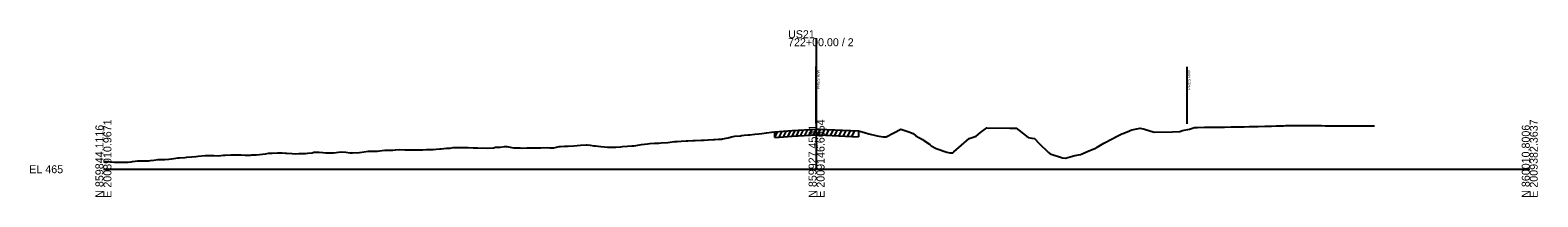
# Model space of a CAD drawing. Extents: x 2008702 to 2066449, y 841632 to 857812.
# Drawn here: x 2065921 to 2066449, y 844204 to 844262 of the extents above; entities that cross this region are included whole.
import ezdxf

# ---------------------------------------------------------------- set-up
doc = ezdxf.new("R2010")
doc.units = 0
for name, color, linetype in [('RD_GPK_XS_Cell', 7, 'Continuous'), ('RD_XS_ExGround', 7, 'Continuous'), ('RD_XS_ExPaveRet', 7, 'Continuous'), ('RD_XS_TX_Box', 7, 'Continuous'), ('RD_XS_TX_Elev_EX', 7, 'Continuous')]:
    doc.layers.add(name, color=color, linetype=linetype)

msp = doc.modelspace()

# ---------------------------------------------------------------- linework, layer by layer
at = {"layer": 'RD_GPK_XS_Cell'}
for p, q in [((2066196.51, 844213.53), (2066196.51, 844259.5)), ((2065946.51, 844213.53), (2066196.51, 844213.53)), ((2066196.51, 844213.53), (2066446.51, 844213.53))]:
    msp.add_line(p, q, dxfattribs=at)
at = {"layer": 'RD_XS_ExGround'}
msp.add_lwpolyline([(2065946.51, 844216.24), (2065947.1, 844216.25), (2065947.63, 844216.22), (2065950.28, 844215.98), (2065952.55, 844215.99), (2065953.46, 844216.04), (2065955.13, 844216.07), (2065956.25, 844216.15), (2065956.65, 844216.21), (2065958.6, 844216.51), (2065959.83, 844216.48), (2065962.4, 844216.52), (2065963.01, 844216.56), (2065964.13, 844216.68), (2065965.66, 844216.92), (2065966.19, 844216.94), (2065968.01, 844217), (2065969.38, 844217.05), (2065970.36, 844217.13), (2065972.71, 844217.52), (2065973.13, 844217.55), (2065975.06, 844217.62), (2065975.74, 844217.73), (2065977.41, 844217.88), (2065978.92, 844217.97), (2065979.76, 844218.07), (2065982.13, 844218.33), (2065985.29, 844218.34), (2065986.82, 844218.29), (2065988.47, 844218.45), (2065989.17, 844218.48), (2065991.13, 844218.55), (2065991.65, 844218.55), (2065993.87, 844218.54), (2065994.84, 844218.56), (2065996.22, 844218.45), (2065998.02, 844218.49), (2065998.57, 844218.6), (2066000.13, 844218.6), (2066001.2, 844218.65), (2066003.27, 844218.97), (2066004.39, 844219.16), (2066005.63, 844219.17), (2066007.57, 844219.28), (2066007.98, 844219.32), (2066009.13, 844219.26), (2066010.33, 844219.17), (2066010.75, 844219.17), (2066012.68, 844219.05), (2066013.93, 844218.97), (2066015.03, 844219.06), (2066017.38, 844219.05), (2066018.13, 844219.19), (2066019.73, 844219.32), (2066020.3, 844219.49), (2066022.08, 844219.47), (2066023.48, 844219.39), (2066024.44, 844219.26), (2066026.79, 844219.24), (2066027.13, 844219.28), (2066029.85, 844219.58), (2066031.49, 844219.51), (2066033.03, 844219.32), (2066033.84, 844219.31), (2066036.25, 844219.38), (2066039.39, 844219.92), (2066041.18, 844219.87), (2066042.58, 844219.87), (2066043.24, 844219.94), (2066045.14, 844220.17), (2066045.76, 844220.24), (2066047.95, 844220.17), (2066048.94, 844220.34), (2066050.3, 844220.51), (2066052.12, 844220.31), (2066054.14, 844220.29), (2066055, 844220.35), (2066055.31, 844220.32), (2066057.35, 844220.39), (2066058.49, 844220.32), (2066059.7, 844220.41), (2066061.67, 844220.46), (2066062.05, 844220.47), (2066063.14, 844220.56), (2066064.41, 844220.67), (2066064.85, 844220.71), (2066066.76, 844220.94), (2066068.04, 844220.95), (2066069.11, 844221.11), (2066071.46, 844221.2), (2066072.14, 844221.19), (2066073.81, 844221.12), (2066074.4, 844221.17), (2066076.16, 844221.03), (2066077.59, 844220.99), (2066081.14, 844220.91), (2066083.22, 844221.08), (2066083.95, 844221.23), (2066085.57, 844221.31), (2066087.13, 844221.53), (2066087.92, 844221.47), (2066090.32, 844221.02), (2066092.62, 844221.05), (2066093.5, 844220.9), (2066094.97, 844221), (2066096.68, 844221.02), (2066097.32, 844221.04), (2066099.14, 844221.04), (2066099.86, 844221.07), (2066102.03, 844221.15), (2066103.05, 844221.03), (2066104.38, 844221.07), (2066106.23, 844221.47), (2066106.73, 844221.55), (2066108.14, 844221.62), (2066109.08, 844221.67), (2066109.41, 844221.66), (2066111.43, 844221.79), (2066112.59, 844221.87), (2066113.78, 844221.93), (2066115.78, 844222.13), (2066116.13, 844222.11), (2066117.14, 844222), (2066118.48, 844221.8), (2066118.96, 844221.76), (2066120.83, 844221.52), (2066122.14, 844221.34), (2066123.19, 844221.32), (2066125.54, 844221.29), (2066126.14, 844221.32), (2066127.89, 844221.44), (2066128.51, 844221.48), (2066130.24, 844221.61), (2066131.69, 844221.69), (2066132.59, 844221.8), (2066135.14, 844222.21), (2066137.29, 844222.48), (2066138.05, 844222.59), (2066139.64, 844222.71), (2066141.24, 844222.73), (2066142, 844222.78), (2066144.42, 844222.94), (2066146.7, 844223.22), (2066147.6, 844223.28), (2066149.05, 844223.4), (2066150.79, 844223.51), (2066151.4, 844223.5), (2066153.14, 844223.56), (2066153.97, 844223.59), (2066156.1, 844223.72), (2066157.15, 844223.79), (2066158.45, 844223.88), (2066160.33, 844223.95), (2066160.81, 844224), (2066162.14, 844224.04), (2066163.16, 844224.1), (2066163.52, 844224.15), (2066165.51, 844224.57), (2066166.7, 844224.87), (2066167.86, 844225.11), (2066169.88, 844225.29), (2066170.21, 844225.34), (2066171.14, 844225.45), (2066172.56, 844225.61), (2066173.06, 844225.66), (2066174.91, 844225.83), (2066176.25, 844225.95), (2066177.26, 844226.05), (2066178.92, 844226.3), (2066180.69, 844226.52), (2066181.92, 844226.7), (2066187.96, 844227.09), (2066196.51, 844227.62), (2066196.82, 844227.64), (2066197.32, 844227.62), (2066211.2, 844226.95), (2066213.35, 844226.38), (2066214.88, 844225.96), (2066217.8, 844225.21), (2066219.91, 844224.95), (2066220.44, 844224.95), (2066220.91, 844224.95), (2066223.54, 844226.32), (2066225.99, 844227.56), (2066228.89, 844226.68), (2066230.35, 844226.11), (2066231.34, 844225.21), (2066233.69, 844223.95), (2066234.14, 844223.63), (2066236.04, 844222.33), (2066236.72, 844221.75), (2066238.4, 844220.75), (2066242.15, 844219.52), (2066243.26, 844219.28), (2066244.26, 844219.28), (2066244.67, 844219.66), (2066250.05, 844224.29), (2066250.7, 844224.5), (2066252.41, 844225.12), (2066254.03, 844226.38), (2066256.16, 844228.08), (2066264.26, 844227.96), (2066266.51, 844227.92), (2066267.43, 844227.2), (2066270.63, 844224.63), (2066271.92, 844224.46), (2066272.85, 844224.33), (2066274.54, 844222.61), (2066277.78, 844219.39), (2066278.39, 844218.91), (2066282.76, 844217.54), (2066283.82, 844217.46), (2066287, 844218.35), (2066288.98, 844218.75), (2066289.64, 844218.99), (2066291.93, 844220), (2066294, 844220.8), (2066294.82, 844221.3), (2066297.21, 844222.7), (2066300.37, 844224.34), (2066301.88, 844225.08), (2066303.55, 844225.9), (2066304.23, 844226.24), (2066306.15, 844227.01), (2066306.73, 844227.23), (2066307.05, 844227.33), (2066309.92, 844227.96), (2066311.5, 844227.61), (2066314.87, 844226.53), (2066321.29, 844226.66), (2066323.86, 844226.73), (2066324.76, 844227.17), (2066327.23, 844227.65), (2066329.01, 844228.16), (2066330.09, 844228.21), (2066332.44, 844228.24), (2066333.15, 844228.25), (2066334.79, 844228.28), (2066335.38, 844228.29), (2066337.15, 844228.32), (2066338.56, 844228.32), (2066339.5, 844228.33), (2066341.85, 844228.36), (2066342.15, 844228.37), (2066344.92, 844228.41), (2066346.44, 844228.45), (2066348.11, 844228.49), (2066351.29, 844228.55), (2066353.6, 844228.59), (2066354.47, 844228.6), (2066355.96, 844228.66), (2066357.65, 844228.74), (2066358.31, 844228.76), (2066360.15, 844228.81), (2066360.84, 844228.82), (2066363.01, 844228.83), (2066364.02, 844228.85), (2066365.36, 844228.83), (2066367.2, 844228.85), (2066367.71, 844228.84), (2066369.15, 844228.85), (2066370.06, 844228.84), (2066370.39, 844228.84), (2066372.41, 844228.82), (2066373.57, 844228.82), (2066374.77, 844228.81), (2066376.75, 844228.8), (2066377.12, 844228.79), (2066378.15, 844228.79), (2066379.47, 844228.79), (2066379.93, 844228.79), (2066381.82, 844228.75), (2066383.12, 844228.74), (2066384.17, 844228.73), (2066386.52, 844228.72), (2066387.15, 844228.71), (2066388.87, 844228.75), (2066389.48, 844228.75), (2066391.22, 844228.73), (2066392.08, 844228.75)], dxfattribs=at)
at = {"layer": 'RD_XS_ExPaveRet'}
for p, q in [((2066181.92, 844224.7), (2066182.96, 844226.77)), ((2066181.92, 844224.7), (2066181.92, 844226.7)), ((2066183.42, 844224.8), (2066184.46, 844226.87)), ((2066184.92, 844224.9), (2066185.96, 844226.96)), ((2066186.42, 844224.99), (2066187.46, 844227.06)), ((2066187.92, 844225.09), (2066188.95, 844227.15)), ((2066187.96, 844225.09), (2066196.51, 844225.62)), ((2066189.42, 844225.18), (2066190.45, 844227.25)), ((2066190.92, 844225.28), (2066191.95, 844227.34)), ((2066192.42, 844225.37), (2066193.45, 844227.43)), ((2066193.92, 844225.46), (2066194.95, 844227.53)), ((2066195.42, 844225.56), (2066196.45, 844227.62)), ((2066196.51, 844225.62), (2066196.82, 844225.64)), ((2066196.82, 844225.64), (2066197.32, 844225.62)), ((2066196.92, 844225.64), (2066197.9, 844227.59)), ((2066197.32, 844225.62), (2066211.2, 844224.95)), ((2066198.42, 844225.57), (2066199.4, 844227.52)), ((2066199.92, 844225.49), (2066200.9, 844227.45)), ((2066201.42, 844225.42), (2066202.4, 844227.37)), ((2066202.92, 844225.35), (2066203.9, 844227.3)), ((2066204.42, 844225.28), (2066205.4, 844227.23)), ((2066205.92, 844225.2), (2066206.9, 844227.16)), ((2066207.42, 844225.13), (2066208.4, 844227.08)), ((2066208.92, 844225.06), (2066209.9, 844227.01)), ((2066211.2, 844226.95), (2066211.2, 844224.95)), ((2066181.92, 844224.7), (2066187.96, 844225.09))]:
    msp.add_line(p, q, dxfattribs=at)
at = {"layer": 'RD_XS_TX_Box'}
for p, q in [((2066196.3, 844249.61), (2066196.3, 844229.61)), ((2066326.3, 844249.47), (2066326.3, 844229.47))]:
    msp.add_line(p, q, dxfattribs=at)

# ---------------------------------------------------------------- texts
at = {"layer": 'RD_GPK_XS_Cell'}
for s, p in [('US21', (2066186.51, 844259.5)), ('722+00.00 / 2', (2066186.51, 844256.7)), ('EL 465', (2065920.51, 844212.13))]:
    msp.add_text(s, height=2.8, dxfattribs=at).set_placement(p)
for s, p in [('E 2008910.9671', (2065949.31, 844203.53)), ('E 2009146.6654', (2066199.31, 844203.53)), ('E 2009382.3637', (2066449.31, 844203.53)), ('N 859844.1116', (2065946.51, 844203.53)), ('N 859927.4561', (2066196.51, 844203.53)), ('N 860010.8006', (2066446.51, 844203.53))]:
    msp.add_text(s, height=2.8, rotation=90, dxfattribs=at).set_placement(p)
at = {"layer": 'RD_XS_TX_Box'}
for p in [(2066197.55, 844241.61), (2066327.55, 844241.47)]:
    msp.add_text('PRES R/W', height=1, rotation=90, dxfattribs=at).set_placement(p)
at = {"layer": 'RD_XS_TX_Elev_EX'}
msp.add_text('472.05', height=0.8, rotation=90, dxfattribs=at).set_placement((2066196.91, 844220.19))

doc.saveas('drawing.dxf')
